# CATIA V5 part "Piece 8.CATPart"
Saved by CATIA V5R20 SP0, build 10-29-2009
Part number: Piece 8
Bounding box of the stored display mesh (mm): x 10.751 to 50.751, y 20.886 to 39.886, z 0 to 4
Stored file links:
  G:\Khaled_CFAO_2011\SIL\SIL_GR1\blaboucarri\Khaled\CAD_CATIA\Piece 8.CATPart
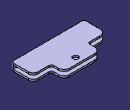
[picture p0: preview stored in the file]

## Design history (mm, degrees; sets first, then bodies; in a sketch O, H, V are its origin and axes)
Parameters
  `petite longueur piece 8` = 10 mm
  `largeur piece 8` = 12 mm
  `epaisseur ` = 4 mm
  `rayon trou` = 1.5 mm
  `distance trou bord` = 2 mm
  `poche largeur` = 2 mm
  `poche profondeur` = 18 mm
  `longueur surélevée` = 20 mm
  `largeur surélevée` = 7 mm
Body1 (main body)
  Sketch1 on xy-plane, origin (0, 0, 0), H (1, 0, 0), V (0, 1, 0)
    line L1 (11.968, 20.8863) -> (49.5056, 20.8863)
    point P1 (50.7507, 20.8863)
    line L2 (50.7507, 22.1314) -> (50.7507, 30.4123)
    point P2 (50.7507, 32.8863)
    line L3 (48.2766, 32.8863) -> (42.0371, 32.8863)
    point P3 (40.7507, 32.8863)
    line L4 (40.7507, 34.1727) -> (40.7507, 36.8865)
    point P4 (40.7507, 39.8863)
    line L5 (37.7508, 39.8863) -> (23.7505, 39.8863)
    point P5 (20.7507, 39.8863)
    line L6 (20.7507, 36.8865) -> (20.7507, 34.0325)
    point P6 (20.7507, 32.8863)
    line L7 (19.6045, 32.8863) -> (14.0543, 32.8863)
    point P7 (10.7507, 32.8863)
    line L8 (10.7507, 29.5827) -> (10.7507, 22.1037)
    circle A1 centre (30.9077, 36.3863) radius 1.5
    point P8 (30.9077, 36.3863)
    arc A2 centre (23.7505, 36.8865) radius 2.9998 from (23.7505, 39.8863) to (20.7507, 36.8865) ccw
    arc A3 centre (37.7508, 36.8865) radius 2.9998 from (37.7508, 39.8863) to (40.7507, 36.8865) cw
    arc A4 centre (48.2766, 30.4123) radius 2.474 from (48.2766, 32.8863) to (50.7507, 30.4123) cw
    arc A5 centre (14.0543, 29.5827) radius 3.3036 from (14.0543, 32.8863) to (10.7507, 29.5827) ccw
    arc A6 centre (49.5056, 22.1314) radius 1.245 from (50.7507, 22.1314) to (49.5056, 20.8863) cw
    arc A7 centre (11.968, 22.1037) radius 1.2173 from (10.7507, 22.1037) to (11.968, 20.8863) ccw
    arc A8 centre (42.0371, 34.1727) radius 1.2864 from (40.7507, 34.1727) to (42.0371, 32.8863) ccw
    arc A9 centre (19.6045, 34.0325) radius 1.1462 from (20.7507, 34.0325) to (19.6045, 32.8863) cw
    radius A1 = 1.5 {= `rayon trou`}
    distance P8 L5 = 3.5 {= `distance trou bord` +`rayon trou`}
    distance P4 P5 = 20 {= `longueur surélevée`}
    radius A2 = 2.9998
    distance P3 P4 = 7 {= `largeur surélevée`}
    radius A3 = 2.9998
    distance P2 P3 = 10 {= `petite longueur piece 8`}
    distance P1 P2 = 12 {= `largeur piece 8`}
    radius A4 = 2.474
    distance P6 P7 = 10 {= `petite longueur piece 8`}
    radius A5 = 3.3036
    radius A6 = 1.245
    radius A7 = 1.2173
    radius A8 = 1.2864
    radius A9 = 1.1462
    horizontal: L1 H, L3 H, L5 H, L7 H
    vertical: L2 V, L4 V, L6 V, L8 V
    coincidence: P6 L3, L5 P5, L6 P5, L5 P4, L4 P4, L3 P2, L2 P2, L7 P7, L8 P7, L2 P1, L1 P1, L4 P3, L3 P3, L6 P6, L7 P6
    tangency: A2 L5, A2 L6, A3 L5, A3 L4, A4 L3, A4 L2, A5 L7, A5 L8, A6 L2, A6 L1, A7 L8, A7 L1, A8 L4, A8 L3, A9 L6, A9 L7
  Pad1: profile Sketch1, direction (0, 0, 1), length 4 {= `epaisseur `}
  Sketch2 on face of Pad1 from Sketch1.L5, origin (0, 39.8863, 0), H (-1, 0, 0), V (0, 0, 1)
    line L1 (-50.7507, 3) -> (-10.7507, 3)
    line L2 (-10.7507, 3) -> (-10.7507, 1)
    line L3 (-10.7507, 1) -> (-50.7507, 1)
    line L4 (-50.7507, 1) -> (-50.7507, 3)
    reference projected line E1 (-10.7507, 0) -> (-10.7507, 4) from edge [face of Pad1 from Sketch1.L8 | face of Pad1 from Sketch1.A5]
    reference intersected line E2 through (0, 0) direction (-1, 0) from xy-plane
    length L2 = 2 {= `poche largeur`}
    length L1 = 40 {= `petite longueur piece 8` *4}
    distance E1 L2 = 0
    distance L3 E2 = 1
    horizontal: L1 H, L3 H
    vertical: L2 V, L4 V
  Pocket1: profile Sketch2, direction (0, -1, 0), length 18 {= `poche profondeur`}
